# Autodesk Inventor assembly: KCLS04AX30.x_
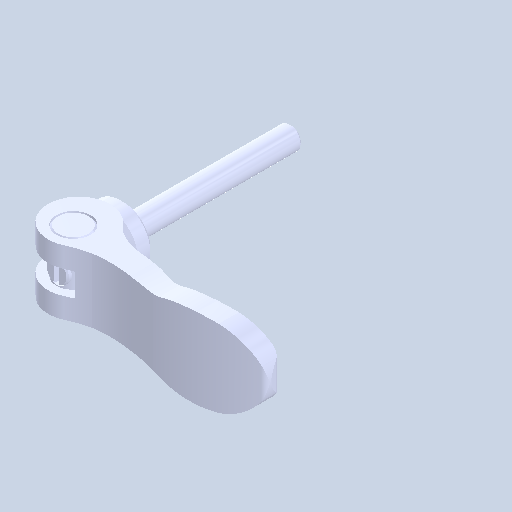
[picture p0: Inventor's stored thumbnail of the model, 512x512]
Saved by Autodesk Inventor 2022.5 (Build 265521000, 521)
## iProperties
Created: 2024-08
Part Number: KCLS04AX30.x_
Document SubType Name: Assembly
Designer: ImaoCorp
Author: ImaoCorp
Sending System: SOLIDWORKS 2022-2022290
MC: AMD64
MC_MODEL: Intel64 Family 6 Model 60 Stepping 3, GenuineIntel
OS: Windows_NT
FRU: Parasolid Version 33.1, build 260,  4-25-2022
FORMAT: text
GUISE: transmit
KEY: FILEKCLS04AX30.x_t
DATE: Thu Aug 29 10:54:11 2024
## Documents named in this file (5)
- Y:\5.更新分\2024年対応\1001_KCL\データ\kcls04ax30\KCLS04AX30.x_.iam
- Y:\5.更新分\2024年対応\1001_KCL\データ\kcls04ax30\KCLS04AX30_01.ipt
- Y:\5.更新分\2024年対応\1001_KCL\データ\kcls04ax30\KCLS04AX30_02.ipt
- Y:\5.更新分\2024年対応\1001_KCL\データ\kcls04ax30\KCLS04AX30_03.ipt
- Y:\5.更新分\2024年対応\1001_KCL\データ\kcls04ax30\KCLS04AX30_04.ipt
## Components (4 placed, 4 different names)
1. KCLS04AX30_01
2. KCLS04AX30_02
3. KCLS04AX30_03
4. KCLS04AX30_04
